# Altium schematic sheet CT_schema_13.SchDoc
size 145 x 119 mm
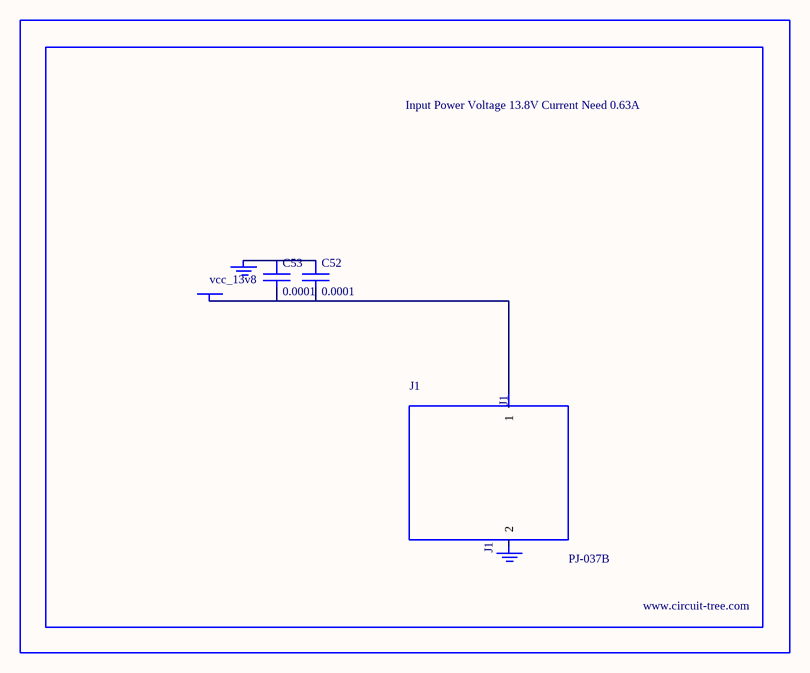
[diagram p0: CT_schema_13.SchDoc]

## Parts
BORDER12  (no value)
C52  0.0001  [EXV-9H]
C53  0.0001  [EXV-9H]
GND_INSTANCE_12_0  (no value)
GND_INSTANCE_12_1  (no value)
J1  PJ-037B  [PJ-037B_PACKAGE]
POWER_INSTANCE_12_0  vcc_13v8

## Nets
NetC52_1: C52.1 C53.1 GND_INSTANCE_12_0.0(GND)
NetC52_2: C52.2 C53.2 J1.1 POWER_INSTANCE_12_0.0(PWR)

Not connected (* = marked no-connect by the designer): GND_INSTANCE_12_1 0(GND); J1 2

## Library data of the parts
BORDER12 = BORDER_PAGE12
C52 C53 = EDK107M035A9HAA
GND_INSTANCE_12_0 GND_INSTANCE_12_1 = GND
POWER_INSTANCE_12_0 = PWR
